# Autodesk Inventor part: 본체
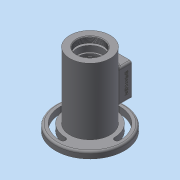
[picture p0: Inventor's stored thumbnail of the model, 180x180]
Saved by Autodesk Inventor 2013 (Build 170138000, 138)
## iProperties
Created: 2017-05
Part Number: 본체
Material: 일반
Document SubType Name: Modeling
Designer: Administrator
Density: 1 g/cm^3
Author: Administrator
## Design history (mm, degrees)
sketch "스케치1"
  geometry: C1 r 31 at (0, 0); 1 further point
  constraints: 1 centre point, 1 coincident
  dimensions: "d0" = 62 diameter of C1
extrude "돌출1" new body sketch "스케치1" distance "d2" = 56; taper "d4" = 0 deg; dims "d3" = 59, "d5" = 0
hole "구멍1" diameter "d13" = 35; stored, may be unused: countersink angle "d17" = 90 deg, drill point angle "d19" = 0 deg; dims "d11" = 10, "d12" = 10, "d14" = 6, "d15" = 52, "d16" = 19, "d18" = 30
sketch "스케치3"
  geometry: C1 r 31 at (0, 0) reference; C2 r 53 at (0, 0)
  constraints: 1 centre point, 1 coincident
  dimensions: "d20" = 106 diameter of C2
extrude "돌출3" join sketch "스케치3" distance "d22" = 10; taper "d23" = 0 deg
sketch "스케치4"
  geometry: C1 r 31 at (0, 0) reference
extrude "돌출4" join sketch "스케치4" distance "d24" = 3; taper "d25" = 0 deg
node "작업 평면2"
sketch "스케치5"
  geometry: L1 (-20, -25)-(20, -25); L2 (20, -25)-(20, 25); L3 (20, 25)-(-20, 25); L4 (-20, 25)-(-20, -25); L5 (-20, -25)-(20, 25); L6 (20, -25)-(-20, 25); 1 further point
  constraints: 12 end point, 2 midpoint, 2 parallel, 1 horizontal, 1 perpendicular
  dimensions: "d27" = 40 distance of L2.end L3.end; "d29" = 50 distance of L1.end L2.end
extrude "돌출5" join sketch "스케치5" stored distance "d30" = 3; taper "d31" = 0 deg
hole "구멍2" diameter "d34" = 40.376; stored, may be unused: countersink angle "d38" = 90 deg, drill point angle "d40" = 0 deg; dims "d32" = 10, "d33" = 10, "d35" = 6, "d36" = 52, "d37" = 19, "d39" = 9
hole "구멍3" diameter "d43" = 40; stored, may be unused: countersink angle "d47" = 90 deg, drill point angle "d49" = 0 deg; dims "d41" = 10, "d42" = 10, "d44" = 6, "d45" = 48, "d46" = 3, "d48" = 12
hole "구멍4" diameter "d52" = 35; stored, may be unused: countersink angle "d56" = 90 deg, drill point angle "d58" = 0 deg; dims "d50" = 10, "d51" = 10, "d53" = 6, "d54" = 35, "d55" = 3, "d57" = 3.25
hole "구멍5" diameter "d61" = 37; stored, may be unused: countersink angle "d65" = 90 deg, drill point angle "d67" = 0 deg; dims "d59" = 10, "d60" = 10, "d62" = 6, "d63" = 35, "d64" = 3, "d66" = 1.75
sketch "스케치6"
  geometry: L1 (0, -59)-(22, -59); L2 (22, -59)-(16, -45); L3 (16, -45)-(0, -45); L4 (0, -45)-(0, -59); L5 (-31, -59)-(31, -59) reference; 4 further points
  constraints: 8 end point, 3 midpoint, 1 horizontal alignment, 1 parallel, 1 perpendicular, 1 vertical, 1 vertical alignment
  dimensions: "d68" = 22 distance of L1.start L1.end; "d70" = 16 distance of L2.end L3.end; "d71" = 14 distance between parallel lines of L1 L3
revolve "회전1" sketch "스케치6" stored, may be unused: angle "d72" = 90 deg
hole "구멍6" diameter "d75" = 20; stored, may be unused: countersink angle "d79" = 90 deg, drill point angle "d81" = 0 deg; dims "d73" = 10, "d74" = 10, "d76" = 6, "d77" = 25, "d78" = 7.3, "d80" = 10
hole "구멍7" diameter "d84" = 33; stored, may be unused: countersink angle "d88" = 90 deg, drill point angle "d90" = 0 deg; dims "d82" = 10, "d83" = 10, "d85" = 6, "d86" = 25, "d87" = 7.3, "d89" = 5
sketch "스케치7"
  geometry: L1 (-11, -16)-(11, -16); L2 (11, -16)-(11, 16); L3 (11, 16)-(-11, 16); L4 (-11, 16)-(-11, -16); L5 (-11, -16)-(11, 16); L6 (11, -16)-(-11, 16); 1 further point
  constraints: 12 end point, 2 midpoint, 2 parallel, 1 horizontal, 1 perpendicular
  dimensions: "d91" = 22 distance of L2.end L3.end; "d93" = 32 distance of L3.end L1.start
extrude "돌출6" cut sketch "스케치7" stored distance "d94" = 3; taper "d95" = 0 deg
hole "구멍8" diameter "d98" = 2.459; stored, may be unused: countersink angle "d102" = 90 deg, drill point angle "d104" = 118 deg; dims "d96" = 4.5, "d97" = 4.5, "d99" = 6, "d100" = 25, "d101" = 7.3, "d103" = 8
sketch "스케치8"
  geometry: C1 r 31 at (0, 0) reference; C2 r 53 at (0, 0) reference; A1 r 41.5 centre (0, 0) between (-41.5, 0) and (0, 41.5); A2 r 4 centre (-41.5, 0) between (-45.5, 0) and (-37.5, 0); A3 r 4 centre (0, 41.5) between (0, 37.5) and (0, 45.5); A4 r 4 centre (41.5, 0) between (45.5, 0) and (37.5, 0); A5 r 4 centre (0, -41.5) between (0, -37.5) and (0, -45.5); A6 r 37.5 centre (0, 0) between (0, 37.5) and (-37.5, 0); A7 r 37.5 centre (0, 0) between (0, -37.5) and (37.5, 0); A8 r 45.5 centre (0, 0) between (0, 45.5) and (-45.5, 0); A9 r 45.5 centre (0, 0) between (0, -45.5) and (45.5, 0)
  constraints: 20 point on circle, 9 centre point, 3 coincident, 3 equal radius, 2 horizontal alignment, 2 vertical alignment
  dimensions: "d111" = 83 diameter of A1; "d115" = 8 diameter of A4; "d116" = 37.5 radius of A6; "d117" = 45.5 radius of A8; "d118" = 45.5 radius of A9; "d119" = 37.5 radius of A7
extrude "돌출7" cut sketch "스케치8" stored distance "d120" = 3; taper "d121" = 0 deg
chamfer "모따기4" distance "d139" = 0.7; stored, may be unused: second distance "d140" = 2, angle "d141" = 30 deg
fillet "모깎기2" dims "d126" = 0.3
fillet "모깎기3" dims "d127" = 3
chamfer "모따기2" distance "d128" = 1; stored, may be unused: second distance "d129" = 2, angle "d130" = 50 deg
fillet "모깎기4" dims "d131" = 3
chamfer "모따기3" distance "d132" = 1; stored, may be unused: second distance "d133" = 2, angle "d134" = 50 deg
sketch "스케치9"
  geometry: L1 (0, 0)-(44, 0) reference; L2 (-34, -13)-(-34, -75) reference; 2 further points
  constraints: 1 other
  dimensions: "d135" = 8 distance from line of point (22, -8) L1; "d136" = 56 distance from line of L2 point (22, -8)
feature "엠보싱1" sketch "스케치9" dims "d137" = 0.5, "d138" = 0
node "솔리드1"
mirror "대칭1"
pattern_linear "직사각형 패턴1" dims "d107" = 31, "d110" = 41
other parameters: "d26" = 44, "d113" = 91, "d114" = 75
